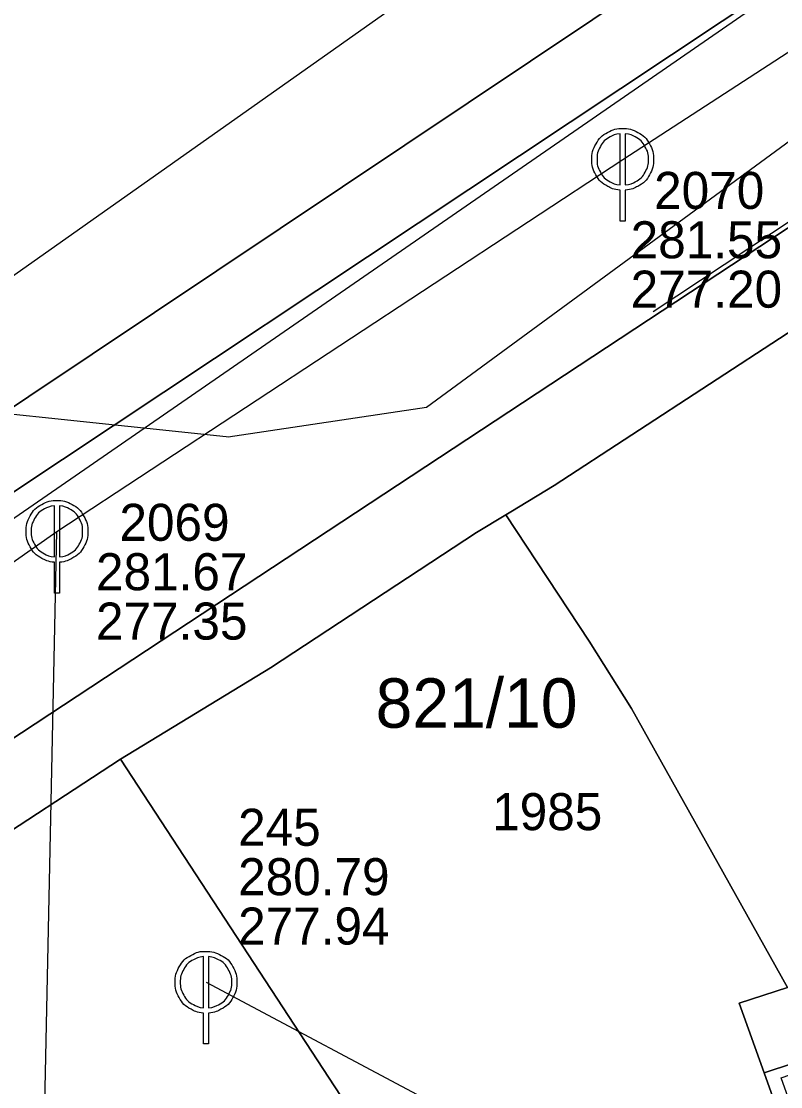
# Model space of a CAD drawing. Extents: x -570698 to -570232, y -1086952 to -1086596.
# Drawn here: x -570394.5 to -570363.74, y -1086781.57 to -1086738.42 of the extents above; entities that cross this region are included whole.
import ezdxf

# ---------------------------------------------------------------- set-up
doc = ezdxf.new("R2010")
doc.units = 0
for name, color, linetype in [('Adresní místo-text', 7, 'Continuous'), ('Default', 7, 'Continuous'), ('Kanalizační přípojka', 7, 'Continuous'), ('Kanalizační stoka', 7, 'Continuous'), ('Kanalizační šachta', 7, 'Continuous'), ('Parcela-polygon', 7, 'Continuous'), ('Parcela-text', 7, 'Continuous'), ('Popis šachty', 7, 'Continuous'), ('Vodovodní řad', 7, 'Continuous')]:
    doc.layers.add(name, color=color, linetype=linetype)

msp = doc.modelspace()

# ---------------------------------------------------------------- linework, layer by layer
at = {"layer": 'Default'}
for points in [[(-570370.243, -1086745.258), (-570370.501, -1086745.24), (-570370.763, -1086745.094), (-570371.06, -1086744.93), (-570371.225, -1086744.633), (-570371.39, -1086744.335), (-570371.39, -1086744.01), (-570371.39, -1086743.683), (-570371.222, -1086743.383), (-570371.053, -1086743.082), (-570370.755, -1086742.921), (-570370.457, -1086742.76), (-570370.14, -1086742.76), (-570369.825, -1086742.76), (-570369.526, -1086742.921), (-570369.227, -1086743.082), (-570369.058, -1086743.383), (-570368.89, -1086743.683), (-570368.89, -1086744.01), (-570368.89, -1086744.335), (-570369.055, -1086744.633), (-570369.22, -1086744.93), (-570369.517, -1086745.094), (-570369.779, -1086745.24), (-570370.037, -1086745.258)], [(-570370.243, -1086742.972), (-570370.44, -1086742.989), (-570370.655, -1086743.104), (-570370.904, -1086743.239), (-570371.043, -1086743.489), (-570371.182, -1086743.739), (-570371.182, -1086744.01), (-570371.182, -1086744.281), (-570371.046, -1086744.528), (-570370.909, -1086744.774), (-570370.66, -1086744.911), (-570370.448, -1086745.031), (-570370.243, -1086745.045)], [(-570370.037, -1086745.045), (-570369.832, -1086745.031), (-570369.618, -1086744.911), (-570369.371, -1086744.774), (-570369.234, -1086744.528), (-570369.098, -1086744.281), (-570369.098, -1086744.01), (-570369.098, -1086743.739), (-570369.238, -1086743.489), (-570369.378, -1086743.239), (-570369.627, -1086743.104), (-570369.84, -1086742.989), (-570370.037, -1086742.972)], [(-570393.163, -1086760.328), (-570393.421, -1086760.31), (-570393.683, -1086760.164), (-570393.98, -1086760), (-570394.145, -1086759.703), (-570394.31, -1086759.405), (-570394.31, -1086759.08), (-570394.31, -1086758.753), (-570394.142, -1086758.453), (-570393.973, -1086758.152), (-570393.675, -1086757.991), (-570393.377, -1086757.83), (-570393.06, -1086757.83), (-570392.745, -1086757.83), (-570392.446, -1086757.991), (-570392.147, -1086758.152), (-570391.978, -1086758.453), (-570391.81, -1086758.753), (-570391.81, -1086759.08), (-570391.81, -1086759.405), (-570391.975, -1086759.703), (-570392.14, -1086760), (-570392.437, -1086760.164), (-570392.699, -1086760.31), (-570392.957, -1086760.328)], [(-570393.163, -1086758.042), (-570393.36, -1086758.059), (-570393.575, -1086758.174), (-570393.824, -1086758.309), (-570393.963, -1086758.559), (-570394.102, -1086758.809), (-570394.102, -1086759.08), (-570394.102, -1086759.351), (-570393.966, -1086759.598), (-570393.829, -1086759.844), (-570393.58, -1086759.981), (-570393.368, -1086760.101), (-570393.163, -1086760.115)], [(-570392.957, -1086760.115), (-570392.752, -1086760.101), (-570392.538, -1086759.981), (-570392.291, -1086759.844), (-570392.154, -1086759.598), (-570392.018, -1086759.351), (-570392.018, -1086759.08), (-570392.018, -1086758.809), (-570392.158, -1086758.559), (-570392.298, -1086758.309), (-570392.547, -1086758.174), (-570392.76, -1086758.059), (-570392.957, -1086758.042)], [(-570387.124, -1086778.587), (-570387.383, -1086778.57), (-570387.644, -1086778.423), (-570387.941, -1086778.259), (-570388.106, -1086777.961), (-570388.271, -1086777.664), (-570388.27, -1086777.339), (-570388.27, -1086777.012), (-570388.102, -1086776.711), (-570387.933, -1086776.411), (-570387.635, -1086776.25), (-570387.337, -1086776.089), (-570387.02, -1086776.09), (-570386.705, -1086776.09), (-570386.406, -1086776.251), (-570386.107, -1086776.412), (-570385.938, -1086776.713), (-570385.77, -1086777.013), (-570385.77, -1086777.34), (-570385.771, -1086777.665), (-570385.936, -1086777.963), (-570386.101, -1086778.261), (-570386.399, -1086778.424), (-570386.66, -1086778.57), (-570386.919, -1086778.587)], [(-570387.122, -1086776.302), (-570387.32, -1086776.319), (-570387.535, -1086776.434), (-570387.784, -1086776.568), (-570387.923, -1086776.818), (-570388.063, -1086777.068), (-570388.063, -1086777.339), (-570388.063, -1086777.61), (-570387.926, -1086777.857), (-570387.79, -1086778.103), (-570387.541, -1086778.24), (-570387.329, -1086778.36), (-570387.124, -1086778.375)], [(-570386.919, -1086778.375), (-570386.713, -1086778.36), (-570386.499, -1086778.241), (-570386.252, -1086778.104), (-570386.115, -1086777.858), (-570385.978, -1086777.611), (-570385.978, -1086777.34), (-570385.978, -1086777.069), (-570386.118, -1086776.819), (-570386.258, -1086776.569), (-570386.507, -1086776.434), (-570386.719, -1086776.319), (-570386.917, -1086776.302)]]:
    msp.add_open_spline(points, degree=3, dxfattribs=at)
at = {"layer": 'Kanalizační přípojka'}
msp.add_lwpolyline([(-570368.91, -1086750.17), (-570362.195, -1086745.73), (-570355.48, -1086741.29), (-570349.857, -1086737.572), (-570344.234, -1086733.853)], dxfattribs=at)
at = {"layer": 'Kanalizační stoka'}
msp.add_line((-570387.02, -1086777.34), (-570311.73, -1086817.32), dxfattribs=at)
for points in [[(-570416.01, -1086763.66), (-570340, -1086709.998), (-570334.265, -1086707.341), (-570324.416, -1086704.737), (-570313.599, -1086705.638), (-570281.39, -1086717.12)], [(-570370.14, -1086744.01), (-570359.365, -1086737.005), (-570348.59, -1086730)], [(-570393.06, -1086759.08), (-570370.14, -1086744.01)], [(-570402.9, -1086765.97), (-570393.06, -1086759.08)], [(-570393.58, -1086783.57), (-570393.32, -1086771.325), (-570393.06, -1086759.08)]]:
    msp.add_lwpolyline(points, dxfattribs=at)
at = {"layer": 'Kanalizační šachta'}
for points in [[(-570370.243, -1086745.045), (-570370.243, -1086742.972)], [(-570370.037, -1086742.972), (-570370.037, -1086745.045)], [(-570370.037, -1086745.258), (-570370.037, -1086746.51), (-570370.243, -1086746.51), (-570370.243, -1086745.258)], [(-570393.163, -1086760.115), (-570393.163, -1086758.042)], [(-570392.957, -1086758.042), (-570392.957, -1086760.115)], [(-570392.957, -1086760.328), (-570392.957, -1086761.58), (-570393.163, -1086761.58), (-570393.163, -1086760.328)], [(-570387.124, -1086778.375), (-570387.122, -1086776.302)], [(-570386.917, -1086776.302), (-570386.919, -1086778.375)], [(-570386.919, -1086778.587), (-570386.919, -1086779.84), (-570387.125, -1086779.84), (-570387.124, -1086778.587)]]:
    msp.add_lwpolyline(points, dxfattribs=at)
at = {"layer": 'Parcela-polygon'}
for points in [[(-570291.64, -1086688.892), (-570302.37, -1086696.04), (-570396.95, -1086758.9), (-570417.85, -1086767.9), (-570426.99, -1086775.07), (-570430.55, -1086777.63), (-570432.81, -1086779.33), (-570437.1, -1086782.56), (-570450.62, -1086793.64), (-570452.87, -1086797.51), (-570456.3, -1086803.42), (-570469.27, -1086814.47), (-570499.22, -1086840.17), (-570503.94, -1086844.12), (-570508.33, -1086847.72), (-570512.7, -1086850.77), (-570519.4, -1086855.31), (-570522.96, -1086857.62), (-570528.66, -1086861.02), (-570535.32, -1086864.67), (-570544.494, -1086869.551)], [(-570471.26, -1086826.6), (-570461.73, -1086819.28), (-570457.91, -1086816.88), (-570450.83, -1086812.94), (-570436.06, -1086800.74), (-570433.95, -1086798.53), (-570429.07, -1086790.91), (-570420.2, -1086784.42), (-570412, -1086778.75), (-570347.1, -1086736.01), (-570341.15, -1086732.35), (-570332.8, -1086726.72), (-570301.2, -1086706.16), (-570286.13, -1086695.6), (-570286.027, -1086695.53)], [(-570347.1, -1086736.01), (-570412, -1086778.75), (-570420.2, -1086784.42), (-570429.07, -1086790.91), (-570433.95, -1086798.53)], [(-570431.51, -1086799.19), (-570427.89, -1086792.8), (-570427.66, -1086792.57), (-570416.86, -1086785.52), (-570417.3, -1086784.9), (-570416.07, -1086784.05), (-570415.6, -1086784.7), (-570409.79, -1086780.91), (-570403.65, -1086776.9), (-570404.13, -1086776.08), (-570402.97, -1086775.36), (-570402.46, -1086776.13), (-570390.48, -1086768.31), (-570384.41, -1086764.61), (-570376.06, -1086759.12), (-570374.88, -1086758.41), (-570374.67, -1086758.28), (-570372.92, -1086757.22), (-570360.33, -1086749.01)]]:
    msp.add_lwpolyline(points, dxfattribs=at)
for points in [[(-570396.95, -1086758.9), (-570302.37, -1086696.04), (-570307.04, -1086695.8), (-570320.65, -1086704.75), (-570323.72, -1086706.78), (-570351.03, -1086724.75), (-570396.74, -1086755.3), (-570401.48, -1086758.74), (-570401.33, -1086758.86), (-570399.38, -1086759.31)], [(-570351.03, -1086724.75), (-570356.5, -1086716.77), (-570360.86, -1086710.41), (-570379.95, -1086716.54), (-570413.68, -1086729.07), (-570423.89, -1086728.17), (-570416.22, -1086738.58), (-570401.54, -1086756.4), (-570400.84, -1086756.79), (-570396.74, -1086755.3)], [(-570374.88, -1086758.41), (-570371.5, -1086763.53), (-570369.78, -1086766.25), (-570363.46, -1086777.55), (-570362.52, -1086777.24), (-570352.48, -1086773.93), (-570358.84, -1086764.07), (-570353.12, -1086760.09), (-570349.53, -1086757.78), (-570348.68, -1086757.23), (-570338.47, -1086750.66), (-570341.95, -1086740.28), (-570345.11, -1086739.23), (-570360.33, -1086749.01), (-570372.92, -1086757.22), (-570374.67, -1086758.28)], [(-570358.49, -1086797.03), (-570359.7, -1086794.79), (-570360.95, -1086790.81), (-570361.2, -1086790.01), (-570364.41, -1086781.01), (-570365.42, -1086778.19), (-570363.46, -1086777.55), (-570369.78, -1086766.25), (-570371.5, -1086763.53), (-570374.88, -1086758.41), (-570376.06, -1086759.12), (-570384.41, -1086764.61), (-570390.48, -1086768.31), (-570369.36, -1086800.59)], [(-570362.52, -1086777.24), (-570363.46, -1086777.55), (-570365.42, -1086778.19), (-570364.41, -1086781.01), (-570331.91, -1086770.3), (-570332.86, -1086767.46), (-570352.48, -1086773.93)], [(-570382.24, -1086792.68), (-570396.13, -1086801.76), (-570389.26, -1086812.25), (-570386.31, -1086810.04), (-570380.97, -1086807.48), (-570374.8, -1086803.82), (-570369.36, -1086800.59), (-570390.48, -1086768.31), (-570402.46, -1086776.13), (-570402.97, -1086775.36), (-570404.13, -1086776.08), (-570403.65, -1086776.9), (-570409.79, -1086780.91), (-570401.38, -1086793.74), (-570387.48, -1086784.65)], [(-570331.91, -1086770.3), (-570364.41, -1086781.01), (-570361.2, -1086790.01), (-570360.86, -1086789.89), (-570363.24, -1086782.57), (-570363.72, -1086781.21), (-570353.74, -1086777.77), (-570353.01, -1086780), (-570337.03, -1086774.66), (-570331.69, -1086772.87), (-570331.11, -1086772.68)]]:
    msp.add_lwpolyline(points, close=True, dxfattribs=at)
at = {"layer": 'Vodovodní řad'}
for points in [[(-570292.345, -1086688.058), (-570314.222, -1086702.909), (-570395.154, -1086758.795)], [(-570426.652, -1086756.545), (-570415.992, -1086758.105), (-570406.517, -1086755.396), (-570401.892, -1086753.59), (-570386.209, -1086755.235), (-570386.119, -1086755.245), (-570378.091, -1086754.042), (-570347.73, -1086731.767), (-570337.558, -1086726.171)]]:
    msp.add_lwpolyline(points, dxfattribs=at)

# ---------------------------------------------------------------- texts
at = {"layer": 'Adresní místo-text'}
msp.add_text('821/10', height=2, dxfattribs=at).set_placement((-570380.151, -1086767.03))
at = {"layer": 'Parcela-text'}
msp.add_text('1985', height=1.5, dxfattribs=at).set_placement((-570375.43, -1086771.18))
at = {"layer": 'Popis šachty'}
for s, p in [('2070', (-570368.869, -1086746.017)), ('281.55', (-570369.819, -1086748.017)), ('277.20', (-570369.819, -1086750.017)), ('2069', (-570390.529, -1086759.461)), ('281.67', (-570391.478, -1086761.461)), ('277.35', (-570391.478, -1086763.461)), ('245', (-570385.721, -1086771.813)), ('280.79', (-570385.721, -1086773.813)), ('277.94', (-570385.721, -1086775.813))]:
    msp.add_text(s, height=1.5, dxfattribs=at).set_placement(p)

doc.saveas('drawing.dxf')
